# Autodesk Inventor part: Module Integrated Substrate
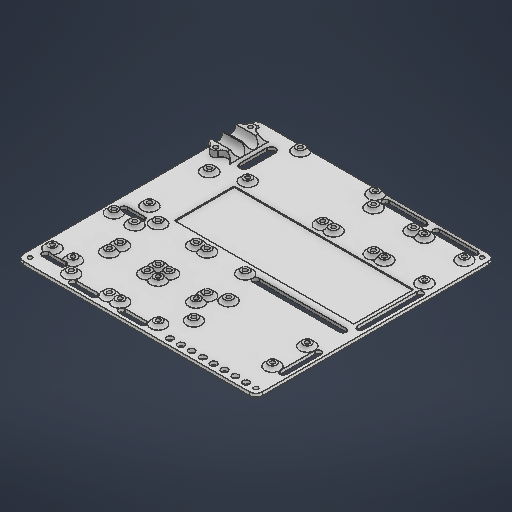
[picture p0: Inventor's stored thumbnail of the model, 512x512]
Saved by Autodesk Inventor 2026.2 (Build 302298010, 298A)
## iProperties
Created: 2026-04
Part Number: Module Integrated Substrate
Material: 일반
Document SubType Name: Modeling
Designer: work
Density: 1 g/cm^3
Appearance: 기본값
Author: work
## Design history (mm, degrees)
sketch "스케치1"
  geometry: L1 (0, 0)-(220, 0); L2 (220, 0)-(220, -220); L3 (220, -220)-(0, -220); L4 (0, -220)-(0, 0); L5 (15.8, -31)-(88.2, -31); L6 (88.2, -31)-(88.2, -63); L7 (88.2, -63)-(15.8, -63); L8 (15.8, -63)-(15.8, -31); L9 (88.2, -47)-(15.8, -47); L10 (52, -31)-(52, -63); L11 (12, -12)-(92, -12); L12 (92, -12)-(92, -82); L13 (92, -82)-(12, -82); L14 (12, -82)-(12, -12); L15 (12, -12)-(92, -82); L16 (92, -12)-(12, -82); L17 (12, -102)-(177, -102); L18 (177, -102)-(177, -157); L19 (177, -157)-(12, -157); L20 (12, -157)-(12, -102); L21 (102, -12)-(137, -12); L22 (137, -12)-(137, -47); L23 (137, -47)-(102, -47); L24 (102, -47)-(102, -12); L25 (102, -12)-(137, -47); L26 (137, -12)-(102, -47); L27 (147, -47)-(147, -12); L28 (182, -47)-(147, -47); L29 (147, -12)-(182, -12); L30 (182, -12)-(147, -47); L31 (147, -12)-(182, -47); L32 (182, -12)-(182, -47); L33 (147, -92)-(147, -57); L34 (182, -92)-(147, -92); L35 (147, -57)-(182, -57); L36 (182, -57)-(147, -92); L37 (147, -57)-(182, -92); L38 (182, -57)-(182, -92); L39 (200, -157)-(200, -102); L40 (213.5, -106.5)-(213.5, -152.5); L41 (213.5, -152.5)-(186.5, -152.5); L42 (186.5, -152.5)-(186.5, -106.5); L43 (186.5, -106.5)-(213.5, -106.5); L44 (213.5, -106.5)-(186.5, -152.5); L45 (213.5, -152.5)-(186.5, -106.5); L46 (12, -129.5)-(220, -129.5); L47 (12, -167)-(48.8, -167); L48 (48.8, -167)-(48.8, -203.8); L49 (48.8, -203.8)-(12, -203.8); L50 (12, -203.8)-(12, -167); L51 (12, -167)-(48.8, -203.8); L52 (48.8, -167)-(12, -203.8); L53 (58.8, -167)-(95.6, -167); L54 (58.8, -203.8)-(58.8, -167); L55 (58.8, -167)-(95.6, -203.8); L56 (95.6, -167)-(58.8, -203.8); L57 (95.6, -203.8)-(58.8, -203.8); L58 (95.6, -167)-(95.6, -203.8); L59 (192, -80.3)-(192, -23.7); L60 (192, -23.7)-(211, -23.7); L61 (211, -23.7)-(211, -80.3); L62 (211, -80.3)-(192, -80.3); L63 (192, -80.3)-(211, -23.7); L64 (192, -23.7)-(211, -80.3)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; C1 r 2 at (6, -6); C2 r 2 at (200, -157); C3 r 2 at (200, -102); C4 r 2 at (15.8, -31); C5 r 2 at (15.8, -63); C6 r 2 at (88.2, -31); C7 r 2 at (88.2, -63); C8 r 2 at (12, -167); C9 r 2 at (12, -203.8); C10 r 2 at (48.8, -203.8); C11 r 2 at (48.8, -167); C12 r 2 at (58.8, -167); C13 r 2 at (58.8, -203.8); C14 r 2 at (95.6, -203.8); C15 r 2 at (95.6, -167); C16 r 2 at (105.6, -167); C17 r 2 at (105.6, -215.5); C18 r 2 at (174.6, -215.5); C19 r 2 at (174.6, -167); C20 r 2 at (211, -23.7); C21 r 2 at (192, -23.7); C22 r 2 at (211, -80.3); C23 r 2 at (192, -80.3); C24 r 2 at (182, -92); C25 r 2 at (182, -57); C26 r 2 at (147, -57); C27 r 2 at (147, -92); C28 r 2 at (137, -12); C29 r 2 at (137, -47); C30 r 2 at (147, -12); C31 r 2 at (182, -12); C32 r 2 at (182, -47); C33 r 2 at (147, -47); C34 r 2 at (102, -12); C35 r 2 at (102, -47); C36 r 2 at (214, -6); C37 r 2 at (214, -214); C38 r 2 at (6, -214); C39 r 2 at (137, -92); C40 r 2 at (137, -57); C41 r 2 at (102, -92); C42 r 2 at (102, -57); C43 r 3 at (25, -6); C44 r 3 at (15, -6); C45 r 3 at (45, -6); C46 r 3 at (35, -6); C47 r 3 at (65, -6); C48 r 3 at (55, -6); C49 r 3 at (85, -6); C50 r 3 at (75, -6); A1 r 3 centre (5.8, -31) between (8.8, -31) and (2.8, -31); A2 r 3 centre (5.8, -63) between (2.8, -63) and (8.8, -63); A3 r 3 centre (6, -102) between (9, -102) and (3, -102); A4 r 3 centre (6, -157) between (3, -157) and (9, -157); A5 r 3 centre (12.9, -214) between (12.9, -211) and (12.9, -217); A6 r 3 centre (47.9, -214) between (47.9, -217) and (47.9, -211); A7 r 3 centre (94.7, -214) between (94.7, -217) and (94.7, -211); A8 r 3 centre (59.7, -214) between (59.7, -211) and (59.7, -217); A9 r 3 centre (12, -92) between (12, -89) and (12, -95); A10 r 3 centre (92, -92) between (92, -95) and (92, -89); A11 r 3 centre (109.5, -6) between (109.5, -3) and (109.5, -9); A12 r 3 centre (129.5, -6) between (129.5, -9) and (129.5, -3); A13 r 3 centre (154.5, -6) between (154.5, -3) and (154.5, -9); A14 r 3 centre (174.5, -6) between (174.5, -9) and (174.5, -3); A15 r 3 centre (193.5, -15.7) between (193.5, -12.7) and (193.5, -18.7); A16 r 3 centre (209.5, -15.7) between (209.5, -18.7) and (209.5, -12.7); A17 r 3 centre (193.5, -88.3) between (193.5, -85.3) and (193.5, -91.3); A18 r 3 centre (209.5, -88.3) between (209.5, -91.3) and (209.5, -85.3); 12 further points
  constraints: 248 end point, 68 centre point, 47 coincident, 39 midpoint, 38 parallel, 36 point on circle, 32 tangent, 19 horizontal, 17 perpendicular, 10 collinear, 7 symmetric about line, 3 vertical, 2 point on line, 23 other
  dimensions: "d0" = 220 distance of L3.end L1.start; "d1" = 220 distance of L1.start L1.end; "d2" = 72.4 distance of L5.start L5.end; "d3" = 32 distance of L7.end L5.start; "d4" = 80 distance of L12.end L13.end; "d5" = 70 distance of L11.end L12.end; "d6" = 4 diameter of C1; "d7" = 6 distance from line of C1.centre L1; "d8" = 6 distance from line of L4 C1.centre; "d9" = 6 horizontal distance of L11.start C1.centre; "d10" = 6 horizontal distance of L11.start C1.centre; "d11" = 165 distance of L18.end L19.end; "d12" = 55 distance of L17.end L18.end; "d13" = 20 distance of L17.start L13.end; "d14" = 35 distance of L22.end L23.end; "d15" = 35 distance of L21.end L22.end; "d16" = 10 distance between parallel lines of L12 L24; "d17" = 35 distance of L28.start L27.start; "d18" = 35 distance of L29.end L28.start; "d19" = 35 distance of L34.start L33.start; "d20" = 35 distance of L35.end L34.start; "d21" = 10 distance between parallel lines of L27 L22; "d22" = 10 distance between parallel lines of L35 L28; "d23" = 55 distance of L39.start L39.end; "d24" = 46 distance of L41.end L42.end; "d25" = 27 distance of L40.end L41.end; "d26" = 4 diameter of C2; "d27" = 4 diameter of C3; "d28" = 20 distance from line of L2 point (200, -129.5); "d29" = 36.8 distance of L48.end L49.end; "d30" = 36.8 distance of L47.end L48.end; "d31" = 10 distance between parallel lines of L47 L19; "d32" = 36.8 distance of L55.end L54.start; "d33" = 36.8 distance of L53.end L55.end; "d34" = 10 distance between parallel lines of L48 L54; "d35" = 56.6 distance of L60.end L61.end; "d36" = 19 distance of L59.end L60.end; "d37" = 5 vertical distance of L28.start L107.start; "d38" = 10 distance between parallel lines of L38 L59; "d39" = 69 distance of L66.end L67.end; "d40" = 48.5 distance of L65.end L66.end; "d41" = 10 distance from line of point (95.6, -185.4) L68; "d42" = 4 diameter of C4; "d43" = 4 diameter of C5; "d44" = 4 diameter of C6; "d45" = 4 diameter of C7; "d46" = 4 diameter of C8; "d47" = 4 diameter of C9; "d48" = 4 diameter of C10; "d49" = 4 diameter of C11; "d50" = 4 diameter of C12; "d51" = 4 diameter of C13; "d52" = 4 diameter of C14; "d53" = 4 diameter of C15; "d54" = 4 diameter of C16; "d55" = 4 diameter of C17; "d56" = 4 diameter of C18; "d57" = 4 diameter of C19; "d58" = 4 diameter of C20; "d59" = 4 diameter of C21; "d60" = 4 diameter of C22; "d61" = 4 diameter of C23; "d62" = 4 diameter of C24; "d63" = 4 diameter of C25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
  node "스케치 - 직사각형 패턴1" dims "d122" = 20, "d125" = 10
extrude "돌출1" new body sketch "스케치1" distance "d127" = 3; taper "d128" = 0 deg
sketch "스케치2"
  geometry: L1 (0, 220)-(-220, 220) reference; L2 (-220, 220)-(-220, 0) reference; L3 (-220, 0)-(0, 0) reference; L4 (0, 0)-(0, 220) reference; L5 (-209.5, 91.3)-(-193.5, 91.3) reference; L6 (-193.5, 85.3)-(-209.5, 85.3) reference; L7 (-193.5, 12.7)-(-209.5, 12.7) reference; L8 (-209.5, 18.7)-(-193.5, 18.7) reference; L9 (-154.5, 3)-(-174.5, 3) reference; L10 (-174.5, 9)-(-154.5, 9) reference; L11 (-109.5, 3)-(-129.5, 3) reference; L12 (-129.5, 9)-(-109.5, 9) reference; L13 (-12, 89)-(-92, 89) reference; L14 (-92, 95)-(-12, 95) reference; L15 (-94.7, 217)-(-59.7, 217) reference; L16 (-59.7, 211)-(-94.7, 211) reference; L17 (-12.9, 211)-(-47.9, 211) reference; L18 (-47.9, 217)-(-12.9, 217) reference; L19 (-9, 102)-(-9, 157) reference; L20 (-3, 157)-(-3, 102) reference; L21 (-8.8, 31)-(-8.8, 63) reference; L22 (-2.8, 63)-(-2.8, 31) reference; L23 (-12, 102)-(-177, 102) reference; L24 (-177, 102)-(-177, 157) reference; L25 (-177, 157)-(-12, 157) reference; L26 (-12, 157)-(-12, 102) reference; C1 r 3 at (-75, 6) reference; C2 r 3 at (-55, 6) reference; C3 r 3 at (-35, 6) reference; C4 r 3 at (-15, 6) reference; C5 r 2 at (-102, 57) reference; C6 r 2 at (-137, 57) reference; C7 r 2 at (-6, 214) reference; C8 r 2 at (-214, 6) reference; C9 r 2 at (-102, 12) reference; C10 r 2 at (-182, 47) reference; C11 r 2 at (-147, 12) reference; C12 r 2 at (-137, 12) reference; C13 r 2 at (-147, 57) reference; C14 r 2 at (-182, 92) reference; C15 r 2 at (-211, 80.3) reference; C16 r 2 at (-211, 23.7) reference; C17 r 2 at (-174.6, 215.5) reference; C18 r 2 at (-105.6, 167) reference; C19 r 2 at (-95.6, 203.8) reference; C20 r 2 at (-58.8, 167) reference; C21 r 2 at (-48.8, 203.8) reference; C22 r 2 at (-12, 167) reference; C23 r 2 at (-88.2, 63) reference; C24 r 2 at (-88.2, 31) reference; C25 r 2 at (-15.8, 63) reference; C26 r 2 at (-15.8, 31) reference; C27 r 2 at (-200, 102) reference; C28 r 2 at (-200, 157) reference; C29 r 2 at (-6, 6) reference; C30 r 2 at (-12, 203.8) reference; C31 r 2 at (-48.8, 167) reference; C32 r 2 at (-58.8, 203.8) reference; C33 r 2 at (-95.6, 167) reference; C34 r 2 at (-105.6, 215.5) reference; C35 r 2 at (-174.6, 167) reference; C36 r 2 at (-192, 23.7) reference; C37 r 2 at (-192, 80.3) reference; C38 r 2 at (-182, 57) reference; C39 r 2 at (-147, 92) reference; C40 r 2 at (-137, 47) reference; C41 r 2 at (-182, 12) reference; C42 r 2 at (-147, 47) reference; C43 r 2 at (-102, 47) reference; C44 r 2 at (-214, 214) reference; C45 r 2 at (-137, 92) reference; C46 r 2 at (-102, 92) reference; C47 r 3 at (-25, 6) reference; C48 r 3 at (-45, 6) reference; C49 r 3 at (-65, 6) reference; C50 r 3 at (-85, 6) reference; C51 r 2 at (-192, 23.7) reference; A1 r 3 centre (-193.5, 88.3) between (-193.5, 85.3) and (-193.5, 91.3) reference; A2 r 3 centre (-209.5, 88.3) between (-209.5, 91.3) and (-209.5, 85.3) reference; A3 r 3 centre (-193.5, 15.7) between (-193.5, 12.7) and (-193.5, 18.7) reference; A4 r 3 centre (-209.5, 15.7) between (-209.5, 18.7) and (-209.5, 12.7) reference; A5 r 3 centre (-154.5, 6) between (-154.5, 3) and (-154.5, 9) reference; A6 r 3 centre (-174.5, 6) between (-174.5, 9) and (-174.5, 3) reference; A7 r 3 centre (-109.5, 6) between (-109.5, 3) and (-109.5, 9) reference; A8 r 3 centre (-129.5, 6) between (-129.5, 9) and (-129.5, 3) reference; A9 r 3 centre (-12, 92) between (-12, 89) and (-12, 95) reference; A10 r 3 centre (-92, 92) between (-92, 95) and (-92, 89) reference; A11 r 3 centre (-59.7, 214) between (-59.7, 211) and (-59.7, 217) reference; A12 r 3 centre (-94.7, 214) between (-94.7, 217) and (-94.7, 211) reference; A13 r 3 centre (-12.9, 214) between (-12.9, 211) and (-12.9, 217) reference; A14 r 3 centre (-47.9, 214) between (-47.9, 217) and (-47.9, 211) reference; A15 r 3 centre (-6, 102) between (-9, 102) and (-3, 102) reference; A16 r 3 centre (-6, 157) between (-3, 157) and (-9, 157) reference; A17 r 3 centre (-5.8, 31) between (-8.8, 31) and (-2.8, 31) reference; A18 r 3 centre (-5.8, 63) between (-2.8, 63) and (-8.8, 63) reference; 39 further points
  constraints: 38 coincident
  node "투영된 루프1"
node "작업 평면1"
sketch "스케치3"
  geometry: L1 (0, 2)-(0, -2) reference; L2 (-3, 2)-(-3, -2) reference; L3 (0, -2)-(3, -2); L4 (3, -2)-(3, -4); L5 (0, -189)-(0, 31) reference; L6 (3, 0)-(-3, 0); L7 (3, 0)-(3, -2); A1 r 3 centre (3, -7) between (3, -4) and (0, -7); 1 further point
  constraints: 8 end point, 3 perpendicular, 2 point on circle, 1 centre point, 1 horizontal, 1 line through centre, 1 midpoint, 1 point on line, 1 tangent
  dimensions: "d129" = 3 distance between parallel lines of L5 L4; "d130" = 8 diameter of L4.end L6
revolve "회전1" sketch "스케치3" stored, may be unused: angle "d131" = 90 deg
sketch "스케치4"
  geometry: L1 (0, -220)-(-220, -220) reference; L2 (0, 0)-(0, -220) reference; L3 (-220, 0)-(0, 0) reference; L4 (-220, -220)-(-220, 0) reference; L5 (-209.5, -91.3)-(-193.5, -91.3) reference; L6 (-193.5, -85.3)-(-209.5, -85.3) reference; L7 (-209.5, -18.7)-(-193.5, -18.7) reference; L8 (-193.5, -12.7)-(-209.5, -12.7) reference; L9 (-174.5, -9)-(-154.5, -9) reference; L10 (-154.5, -3)-(-174.5, -3) reference; L11 (-129.5, -9)-(-109.5, -9) reference; L12 (-109.5, -3)-(-129.5, -3) reference; L13 (-92, -95)-(-12, -95) reference; L14 (-12, -89)-(-92, -89) reference; L15 (-94.7, -217)-(-59.7, -217) reference; L16 (-59.7, -211)-(-94.7, -211) reference; L17 (-47.9, -217)-(-12.9, -217) reference; L18 (-12.9, -211)-(-47.9, -211) reference; L19 (-3, -157)-(-3, -102) reference; L20 (-9, -102)-(-9, -157) reference; L21 (-2.8, -63)-(-2.8, -31) reference; L22 (-8.8, -31)-(-8.8, -63) reference; L23 (-12, -102)-(-177, -102) reference; L24 (-12, -157)-(-12, -102) reference; L25 (-177, -157)-(-12, -157) reference; L26 (-177, -102)-(-177, -157) reference; L27 (-241.244, -269.242)-(23.244, -269.242); L28 (23.244, -269.242)-(23.244, 32.225); L29 (23.244, 32.225)-(-241.244, 32.225); L30 (-241.244, 32.225)-(-241.244, -269.242); C1 r 3 at (-75, -6) reference; C2 r 3 at (-55, -6) reference; C3 r 3 at (-35, -6) reference; C4 r 3 at (-15, -6) reference; C5 r 2 at (-102, -57) reference; C6 r 2 at (-137, -57) reference; C7 r 2 at (-6, -214) reference; C8 r 2 at (-214, -6) reference; C9 r 2 at (-102, -12) reference; C10 r 2 at (-182, -47) reference; C11 r 2 at (-147, -12) reference; C12 r 2 at (-137, -12) reference; C13 r 2 at (-147, -57) reference; C14 r 2 at (-182, -92) reference; C15 r 2 at (-211, -80.3) reference; C16 r 2 at (-211, -23.7) reference; C17 r 2 at (-174.6, -215.5) reference; C18 r 2 at (-105.6, -167) reference; C19 r 2 at (-95.6, -203.8) reference; C20 r 2 at (-58.8, -167) reference; C21 r 2 at (-48.8, -203.8) reference; C22 r 2 at (-12, -167) reference; C23 r 2 at (-88.2, -63) reference; C24 r 2 at (-88.2, -31) reference; C25 r 2 at (-15.8, -63) reference; C26 r 2 at (-15.8, -31) reference; C27 r 2 at (-200, -102) reference; C28 r 2 at (-200, -157) reference; C29 r 2 at (-6, -6) reference; C30 r 2 at (-12, -203.8) reference; C31 r 2 at (-48.8, -167) reference; C32 r 2 at (-58.8, -203.8) reference; C33 r 2 at (-95.6, -167) reference; C34 r 2 at (-105.6, -215.5) reference; C35 r 2 at (-174.6, -167) reference; C36 r 2 at (-192, -23.7) reference; C37 r 2 at (-192, -80.3) reference; C38 r 2 at (-182, -57) reference; C39 r 2 at (-147, -92) reference; C40 r 2 at (-137, -47) reference; C41 r 2 at (-182, -12) reference; C42 r 2 at (-147, -47) reference; C43 r 2 at (-102, -47) reference; C44 r 2 at (-214, -214) reference; C45 r 2 at (-137, -92) reference; C46 r 2 at (-102, -92) reference; C47 r 3 at (-25, -6) reference; C48 r 3 at (-45, -6) reference; C49 r 3 at (-65, -6) reference; C50 r 3 at (-85, -6) reference; A1 r 3 centre (-209.5, -88.3) between (-209.5, -85.3) and (-209.5, -91.3) reference; A2 r 3 centre (-193.5, -88.3) between (-193.5, -91.3) and (-193.5, -85.3) reference; A3 r 3 centre (-193.5, -15.7) between (-193.5, -18.7) and (-193.5, -12.7) reference; A4 r 3 centre (-209.5, -15.7) between (-209.5, -12.7) and (-209.5, -18.7) reference; A5 r 3 centre (-154.5, -6) between (-154.5, -9) and (-154.5, -3) reference; A6 r 3 centre (-174.5, -6) between (-174.5, -3) and (-174.5, -9) reference; A7 r 3 centre (-109.5, -6) between (-109.5, -9) and (-109.5, -3) reference; A8 r 3 centre (-129.5, -6) between (-129.5, -3) and (-129.5, -9) reference; A9 r 3 centre (-12, -92) between (-12, -95) and (-12, -89) reference; A10 r 3 centre (-92, -92) between (-92, -89) and (-92, -95) reference; A11 r 3 centre (-94.7, -214) between (-94.7, -211) and (-94.7, -217) reference; A12 r 3 centre (-59.7, -214) between (-59.7, -217) and (-59.7, -211) reference; A13 r 3 centre (-12.9, -214) between (-12.9, -217) and (-12.9, -211) reference; A14 r 3 centre (-47.9, -214) between (-47.9, -211) and (-47.9, -217) reference; A15 r 3 centre (-6, -102) between (-3, -102) and (-9, -102) reference; A16 r 3 centre (-6, -157) between (-9, -157) and (-3, -157) reference; A17 r 3 centre (-5.8, -31) between (-2.8, -31) and (-8.8, -31) reference; A18 r 3 centre (-5.8, -63) between (-8.8, -63) and (-2.8, -63) reference; 1 further point
  constraints: 8 end point, 2 parallel, 1 horizontal, 1 perpendicular
extrude "돌출2" cut sketch "스케치4" extent not by distance; stored distance "d132" = 0; taper "d133" = 0 deg
extrude "돌출3" join sketch "스케치1" distance "d134" = 2; taper "d135" = 0 deg
fillet "모깎기1" dims "d136" = 6
sketch "스케치6"
  geometry: L1 (-2, 3)-(2, 3) reference; L2 (208, 3)-(0, 3) reference; L3 (10, 3)-(10, 8.5); L4 (18, 8.5)-(10, 8.5); L5 (18, 8.5)-(30, 8.5); L6 (30, 8.5)-(38, 8.5); L7 (38, 8.5)-(38, 3); C1 r 5.5 at (18, 8.5); C2 r 5.5 at (30, 8.5); 8 further points
  constraints: 10 end point, 3 horizontal, 3 point on line, 2 centre point, 1 midpoint, 1 perpendicular, 1 tangent, 1 vertical
  dimensions: "d137" = 11 diameter of C1; "d138" = 8 distance of L3.end L4.start; "d139" = 10 distance from line of L3 point (0, 3); "d140" = 12 distance of L4.start L5.end; "d141" = 11 diameter of C2; "d142" = 12 distance of L4.start L6.start; "d143" = 8 distance of L6.start L6.end
extrude "돌출4" join sketch "스케치6" distance "d144" = 18; taper "d145" = 0 deg
sketch "스케치7" dims "d147" = 8
  geometry: L1 (0, 2.5)-(18, 2.5) reference; L2 (9, 2.5)-(9, -25.5); L3 (18, -25.5)-(0, -25.5) reference; L4 (18, -25.5)-(0, -25.5) reference; L5 (0, -25.5)-(0, -195.5) reference; L6 (6, -201.5)-(214, -201.5) reference; L7 (220, -195.5)-(220, 12.5) reference; L8 (214, 18.5)-(119.762, 18.5) reference; L9 (109.038, 18.5)-(50.762, 18.5) reference; L10 (40.038, 18.5)-(6, 18.5) reference; L11 (0, 12.5)-(0, 2.5) reference; L12 (0, 2.5)-(18, 2.5) reference; L13 (18, 2.5)-(18, -5.5) reference; L14 (18, -5.5)-(18, -17.5) reference; L15 (18, -17.5)-(18, -25.5) reference; L16 (10.5, -110.2)-(26.5, -110.2) reference; L17 (23.101, -116.2)-(13.899, -116.2) reference; L18 (26.5, -188.8)-(10.5, -188.8) reference; L19 (13.899, -182.8)-(23.101, -182.8) reference; L20 (208, -112.5)-(128, -112.5) reference; L21 (128, -106.5)-(208, -106.5) reference; L22 (125.3, 15.5)-(160.3, 15.5) reference; L23 (160.3, 9.5)-(125.3, 9.5) reference; L24 (207.1, 9.5)-(172.1, 9.5) reference; L25 (172.1, 15.5)-(207.1, 15.5) reference; L26 (211, -99.5)-(211, -44.5) reference; L27 (217, -44.5)-(217, -99.5) reference; L28 (211.2, -170.5)-(211.2, -138.5) reference; L29 (217.2, -138.5)-(217.2, -170.5) reference; L30 (208, -99.5)-(43, -99.5) reference; L31 (43, -99.5)-(43, -44.5) reference; L32 (43, -44.5)-(208, -44.5) reference; L33 (208, -44.5)-(208, -99.5) reference; L34 (110.5, -198.5)-(90.5, -198.5) reference; L35 (65.5, -198.5)-(45.5, -198.5) reference; L36 (45.5, -192.5)-(65.5, -192.5) reference; L37 (90.5, -192.5)-(110.5, -192.5) reference; L38 (0, 0)-(0, 2.5) reference; L39 (0, 0)-(18, 0) reference; L40 (18, 2.5)-(18, 0) reference; L41 (0, 2.5)-(18, 2.5) reference; L42 (0, -25.5)-(0, -23) reference; L43 (0, -25.5)-(18, -25.5) reference; L44 (18, -23)-(18, -25.5) reference; L45 (0, -23)-(18, -23) reference; L46 (18, -11.5)-(0, -11.5); L47 (0, -25.5)-(18, -25.5) reference; L48 (9, -27.5)-(9, -25.5); L49 (9, 4.5)-(9, 2.5); C1 r 3 at (145, -195.5) reference; C2 r 3 at (165, -195.5) reference; C3 r 3 at (185, -195.5) reference; C4 r 3 at (205, -195.5) reference; C5 r 2 at (214, 12.5) reference; C6 r 2 at (6, -195.5) reference; C7 r 2 at (214, -195.5) reference; C8 r 2 at (6, 12.5) reference; C9 r 3 at (195, -195.5) reference; C10 r 3 at (175, -195.5) reference; C11 r 3 at (155, -195.5) reference; C12 r 3 at (135, -195.5) reference; C13 r 7 at (208, 2.3) reference; C14 r 7 at (20, -44.5) reference; C15 r 7 at (131.8, -170.5) reference; C16 r 7 at (131.8, -138.5) reference; C17 r 7 at (38, -109.5) reference; C18 r 7 at (20, -99.5) reference; C19 r 7 at (45.4, -34.5) reference; C20 r 7 at (124.4, 2.3) reference; C21 r 7 at (208, -34.5) reference; C22 r 2 at (9, -27.5); C23 r 2 at (9, 4.5); A1 r 6 centre (6, -195.5) between (0, -195.5) and (6, -201.5) reference; A2 r 6 centre (214, -195.5) between (214, -201.5) and (220, -195.5) reference; A3 r 6 centre (214, 12.5) between (220, 12.5) and (214, 18.5) reference; A4 r 7 centre (114.4, 14) between (109.038, 18.5) and (119.762, 18.5) reference; A5 r 7 centre (45.4, 14) between (40.038, 18.5) and (50.762, 18.5) reference; A6 r 6 centre (6, 12.5) between (6, 18.5) and (0, 12.5) reference; A7 r 7 centre (9, -121.2) between (7.716, -114.319) and (13.899, -116.2) reference; A8 r 3 centre (10.5, -113.2) between (10.5, -110.2) and (7.716, -114.319) reference; A9 r 3 centre (26.5, -113.2) between (29.284, -114.319) and (26.5, -110.2) reference; A10 r 7 centre (28, -121.2) between (23.101, -116.2) and (29.284, -114.319) reference; A11 r 7 centre (28, -177.8) between (29.284, -184.681) and (23.101, -182.8) reference; A12 r 3 centre (26.5, -185.8) between (26.5, -188.8) and (29.284, -184.681) reference; A13 r 3 centre (10.5, -185.8) between (7.716, -184.681) and (10.5, -188.8) reference; A14 r 7 centre (9, -177.8) between (13.899, -182.8) and (7.716, -184.681) reference; A15 r 3 centre (208, -109.5) between (208, -112.5) and (208, -106.5) reference; A16 r 3 centre (128, -109.5) between (125, -109.5) and (128, -112.5) reference; A17 r 3 centre (128, -109.5) between (128, -106.5) and (125, -109.5) reference; A18 r 3 centre (160.3, 12.5) between (160.3, 9.5) and (160.3, 15.5) reference; A19 r 3 centre (125.3, 12.5) between (125.3, 15.5) and (125.3, 9.5) reference; A20 r 3 centre (207.1, 12.5) between (207.1, 9.5) and (207.1, 15.5) reference; A21 r 3 centre (172.1, 12.5) between (172.1, 15.5) and (172.1, 9.5) reference; A22 r 3 centre (214, -99.5) between (211, -99.5) and (217, -99.5) reference; A23 r 3 centre (214, -44.5) between (217, -44.5) and (211, -44.5) reference; A24 r 3 centre (214.2, -170.5) between (211.2, -170.5) and (217.2, -170.5) reference; A25 r 3 centre (214.2, -138.5) between (217.2, -138.5) and (211.2, -138.5) reference; A26 r 7 centre (38, -154.5) between (33.101, -149.5) and (42.899, -149.5) reference; A27 r 7 centre (38, -144.5) between (42.899, -149.5) and (33.101, -149.5) reference; A28 r 7 centre (73, -109.5) between (78, -104.601) and (78, -114.399) reference; A29 r 7 centre (83, -109.5) between (78, -114.399) and (78, -104.601) reference; A30 r 7 centre (118, -144.5) between (122.899, -149.5) and (113.101, -149.5) reference; A31 r 7 centre (118, -154.5) between (113.101, -149.5) and (122.899, -149.5) reference; A32 r 7 centre (73, -144.5) between (78, -139.601) and (68.101, -149.5) reference; A33 r 7 centre (83, -144.5) between (87.899, -149.5) and (78, -139.601) reference; A34 r 7 centre (83, -154.5) between (78, -159.399) and (87.899, -149.5) reference; A35 r 7 centre (73, -154.5) between (68.101, -149.5) and (78, -159.399) reference; A36 r 7 centre (124.4, -34.5) between (119.4, -39.399) and (119.4, -29.601) reference; A37 r 7 centre (114.4, -34.5) between (119.4, -29.601) and (119.4, -39.399) reference; A38 r 7 centre (171.2, -34.5) between (166.2, -39.399) and (166.2, -29.601) reference; A39 r 7 centre (161.2, -34.5) between (166.2, -29.601) and (166.2, -39.399) reference; A40 r 7 centre (161.2, 2.3) between (166.2, 7.199) and (166.2, -2.599) reference; A41 r 7 centre (171.2, 2.3) between (166.2, -2.599) and (166.2, 7.199) reference; A42 r 7 centre (118, -189.5) between (113.415, -194.789) and (111.833, -192.813) reference; A43 r 3 centre (110.5, -195.5) between (110.5, -198.5) and (113.415, -194.789) reference; A44 r 3 centre (90.5, -195.5) between (87.585, -194.789) and (90.5, -198.5) reference; A45 r 7 centre (83, -189.5) between (78, -194.399) and (87.585, -194.789) reference; A46 r 7 centre (73, -189.5) between (68.415, -194.789) and (78, -194.399) reference; A47 r 3 centre (65.5, -195.5) between (65.5, -198.5) and (68.415, -194.789) reference; A48 r 3 centre (45.5, -195.5) between (42.585, -194.789) and (45.5, -198.5) reference; A49 r 7 centre (38, -189.5) between (44.167, -192.813) and (42.585, -194.789) reference; A50 r 3 centre (45.5, -195.5) between (45.5, -192.5) and (44.167, -192.813) reference; A51 r 3 centre (65.5, -195.5) between (66.833, -192.813) and (65.5, -192.5) reference; A52 r 7 centre (73, -189.5) between (78, -184.601) and (66.833, -192.813) reference; A53 r 7 centre (83, -189.5) between (89.167, -192.813) and (78, -184.601) reference; A54 r 3 centre (90.5, -195.5) between (90.5, -192.5) and (89.167, -192.813) reference; A55 r 3 centre (110.5, -195.5) between (111.833, -192.813) and (110.5, -192.5) reference; A56 r 5.75 centre (18, -31.25) between (18, -25.5) and (12.692, -29.038); A57 r 5.75 centre (0, -31.25) between (5.308, -29.038) and (0, -25.5); A58 r 5.75 centre (0, 8.25) between (0, 2.5) and (5.308, 6.038); A59 r 5.75 centre (18, 8.25) between (12.692, 6.038) and (18, 2.5); 12 further points
  constraints: 12 symmetric about line, 8 end point, 8 point on circle, 6 centre point, 4 midpoint, 3 horizontal alignment, 2 coincident, 2 horizontal, 1 collinear, 1 tangent, 11 other
  dimensions: "d146" = 4 diameter of C22; "d148" = 2 distance of L48.end C22.centre
  node "투영된 루프4"
  node "투영된 루프5"
  node "투영된 루프6"
extrude "돌출5" join sketch "스케치7" stored distance "d149" = 18; taper "d150" = 0 deg
extrude "돌출6" cut sketch "스케치7" extent not by distance; stored distance "d151" = 10; taper "d152" = 0 deg
chamfer "모따기1" distance "d153" = 5.5; stored, may be unused: second distance "d154" = 2, angle "d155" = 45 deg
sketch "스케치8"
  geometry: L1 (-202, 190.5)-(-202, 189.5) reference; L2 (-202, 190)-(-188.5, 190); L3 (-188.5, 202.5)-(-188.5, 177.5); L4 (-192.5, 202.5)-(-192.5, 177.5); L5 (-184.5, 177.5)-(-184.5, 202.5); A1 r 4 centre (-188.5, 202.5) between (-184.5, 202.5) and (-192.5, 202.5); A2 r 4 centre (-188.5, 177.5) between (-192.5, 177.5) and (-184.5, 177.5); A3 r 5.5 centre (-202, 184) between (-196.5, 184) and (-202, 189.5) reference; 1 further point
  constraints: 10 end point, 4 point on circle, 4 tangent, 2 centre point, 2 midpoint, 1 horizontal, 1 parallel, 1 vertical
  dimensions: "d156" = 25 distance of L3.start L3.end; "d157" = 4 radius of A2; "d158" = 8 distance edge to line of A3 L3
extrude "돌출7" cut sketch "스케치8" extent not by distance; stored distance "d159" = 0; taper "d160" = 0 deg
node "솔리드1"
feature "스케치 연계 패턴1"
node "투영된 루프2"
node "투영된 루프3"
